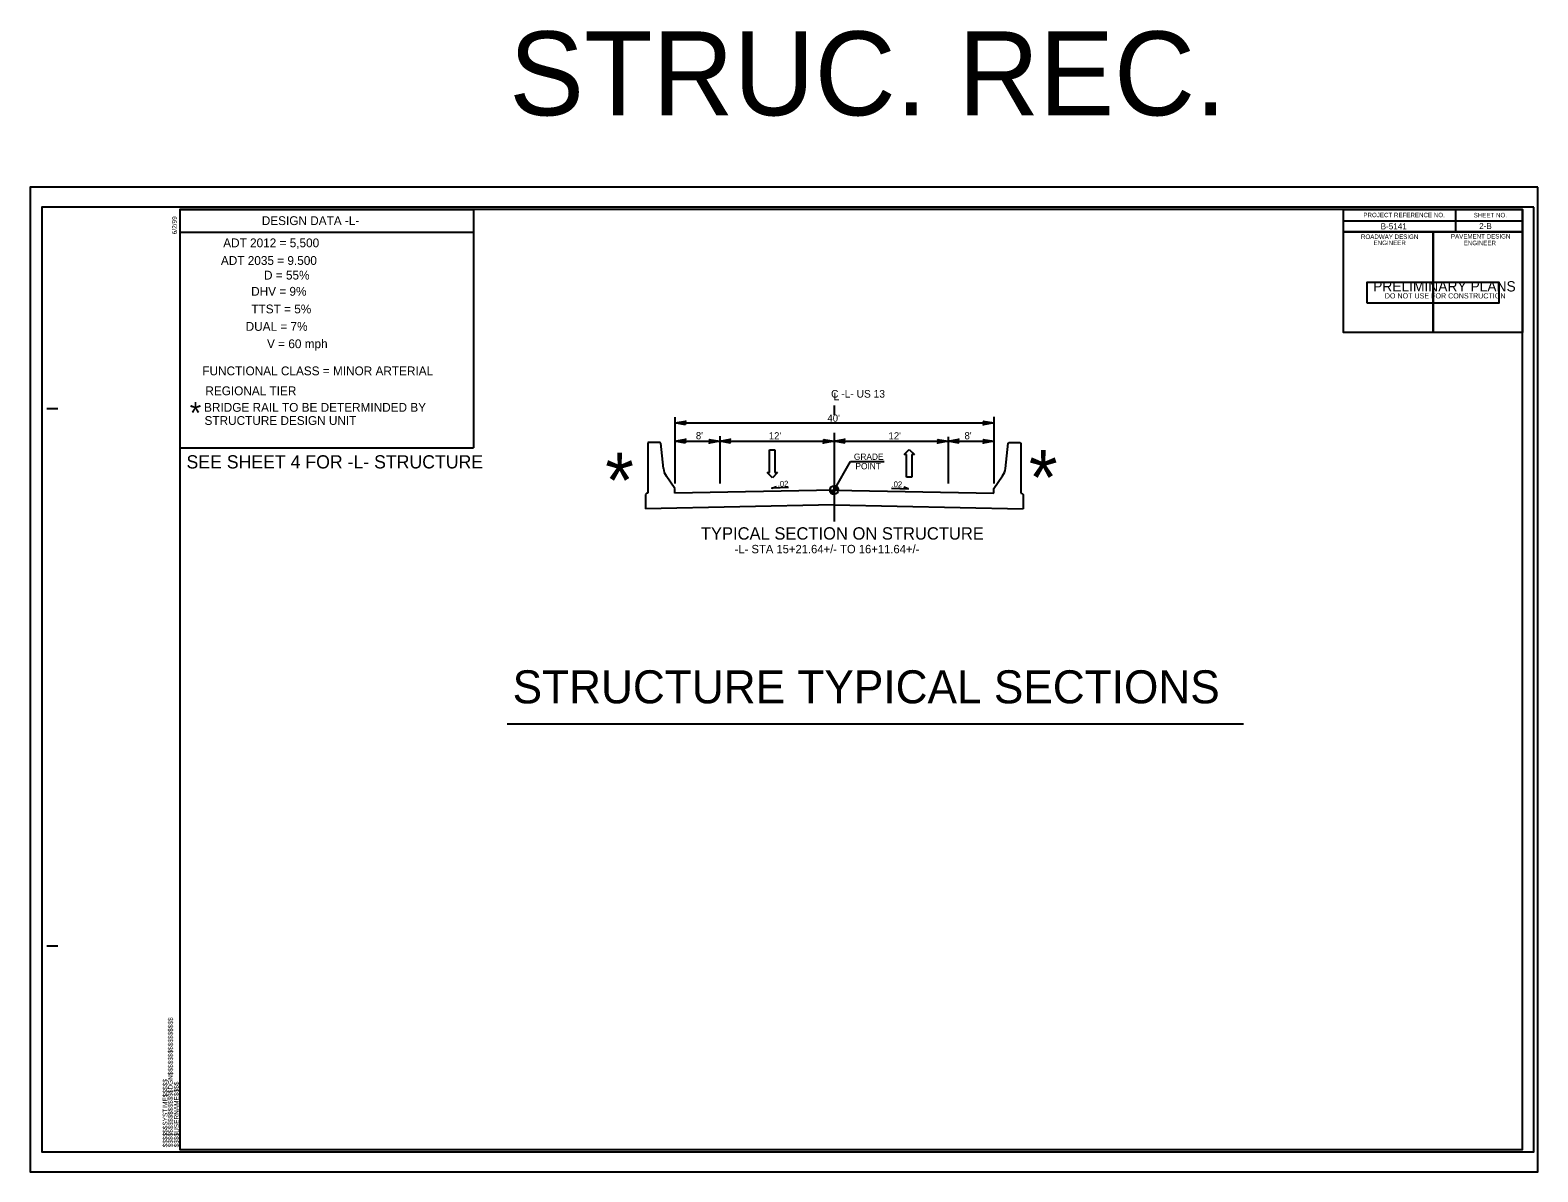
# Model space of a CAD drawing. Extents: x 9470 to 10081, y 10104 to 10463.
# Drawn here: x 9470.2 to 9739.6, y 10236.8 to 10440.9 of the extents above; entities that cross this region are included whole.
import ezdxf

# ---------------------------------------------------------------- set-up
doc = ezdxf.new("R2010")
doc.units = 0
for name, color, linetype in [('Default', 7, 'Continuous'), ('Old_Level_1', 7, 'Continuous'), ('Old_Level_11', 7, 'Continuous'), ('Old_Level_2', 7, 'Continuous'), ('Old_Level_3', 7, 'Continuous'), ('Old_Level_32', 7, 'Continuous'), ('Old_Level_33', 7, 'Continuous'), ('Prop Dimension Text', 7, 'Continuous'), ('Sheet Cutting Line CELL', 7, 'Continuous'), ('Sheet Data Field CELL', 7, 'Continuous'), ('Sheet Plot Border Inside CELL', 7, 'Continuous'), ('Sheet Plot Border Outside CELL', 7, 'Continuous'), ('Sheet Sticker Preliminary CELL', 7, 'Continuous'), ('Sheet Typical CELL', 7, 'Continuous'), ('Typical Terminator CELL', 7, 'Continuous'), ('Typical Text Grade Point CELL', 7, 'Continuous')]:
    doc.layers.add(name, color=color, linetype=linetype)

msp = doc.modelspace()

# ---------------------------------------------------------------- linework, layer by layer
at = {"layer": 'Default'}
for p, q in [((9602.36, 10361.79), (9602.36, 10365.83)), ((9602.36, 10365.83), (9603.31, 10365.83)), ((9603.31, 10365.83), (9603.31, 10361.79)), ((9626.41, 10365.01), (9627.3, 10365.92)), ((9627.3, 10365.92), (9628.23, 10365.01)), ((9626.84, 10365.01), (9626.41, 10365.01)), ((9626.84, 10360.97), (9626.84, 10365.01)), ((9628.23, 10365.01), (9627.79, 10365.01)), ((9627.79, 10365.01), (9627.79, 10360.97)), ((9602.85, 10360.88), (9601.93, 10361.79)), ((9601.93, 10361.79), (9602.36, 10361.79)), ((9603.75, 10361.79), (9602.85, 10360.88)), ((9603.31, 10361.79), (9603.75, 10361.79)), ((9627.79, 10360.97), (9626.84, 10360.97))]:
    msp.add_line(p, q, dxfattribs=at)
at = {"layer": 'Old_Level_1'}
for p, q in [((9613.87, 10373.79), (9613.87, 10372.13)), ((9585.44, 10371.69), (9585.44, 10359.83)), ((9642.42, 10371.76), (9642.42, 10359.83)), ((9585.44, 10370.66), (9642.42, 10370.66)), ((9593.47, 10368.33), (9593.47, 10359.83)), ((9613.87, 10368.88), (9613.87, 10353.08)), ((9634.27, 10370.66), (9637.67, 10370.66)), ((9634.27, 10368.17), (9634.27, 10359.83)), ((9580.72, 10367.19), (9580.61, 10367.09)), ((9580.61, 10367.09), (9580.61, 10358.11)), ((9582.78, 10367.19), (9580.72, 10367.19)), ((9582.9, 10367.07), (9582.78, 10367.19)), ((9583.38, 10362.53), (9582.9, 10367.07)), ((9585.44, 10367.4), (9593.47, 10367.4)), ((9593.47, 10367.4), (9613.87, 10367.4)), ((9613.87, 10367.4), (9634.27, 10367.4)), ((9634.27, 10367.4), (9642.42, 10367.4)), ((9644.49, 10362.53), (9644.97, 10367.07)), ((9644.97, 10367.07), (9645.09, 10367.19)), ((9645.09, 10367.19), (9647.14, 10367.19)), ((9647.14, 10367.19), (9647.25, 10367.08)), ((9647.25, 10367.08), (9647.25, 10358.11)), ((9613.87, 10358.68), (9616.8, 10363.8)), ((9585.44, 10358.97), (9583.87, 10361.2)), ((9642.42, 10358.96), (9643.99, 10361.2)), ((9580.4, 10358.11), (9580.19, 10357.9)), ((9580.19, 10357.9), (9580.19, 10356.41)), ((9580.61, 10358.11), (9580.4, 10358.11)), ((9585.44, 10358.11), (9585.44, 10358.97)), ((9613.87, 10358.68), (9585.44, 10358.11)), ((9613.1, 10358.68), (9613.87, 10358.68)), ((9613.87, 10358.68), (9613.87, 10359.45)), ((9614.63, 10358.68), (9613.87, 10358.68)), ((9613.87, 10357.92), (9613.87, 10358.68)), ((9613.87, 10358.68), (9613.87, 10357.92)), ((9613.87, 10358.68), (9642.42, 10358.11)), ((9642.42, 10358.11), (9642.42, 10358.96)), ((9647.25, 10358.11), (9647.46, 10358.11)), ((9647.46, 10358.11), (9647.67, 10357.9)), ((9647.67, 10357.9), (9647.67, 10356.41)), ((9580.19, 10356.41), (9580.19, 10355.34)), ((9613.87, 10356.01), (9580.19, 10355.34)), ((9613.87, 10356.01), (9647.67, 10355.34)), ((9647.67, 10356.41), (9647.67, 10355.34))]:
    msp.add_line(p, q, dxfattribs=at)
for points in [[(9605.76, 10359.1), (9602.78, 10359), (9603.56, 10359.29)], [(9613.11, 10358.68), (9613.11, 10358.6)], [(9613.12, 10358.68), (9613.12, 10358.51)], [(9613.14, 10358.68), (9613.14, 10358.45)], [(9613.15, 10358.68), (9613.15, 10358.41)], [(9613.17, 10358.68), (9613.17, 10358.37)], [(9613.18, 10358.68), (9613.18, 10358.34)], [(9613.2, 10358.68), (9613.2, 10358.31)], [(9613.21, 10358.68), (9613.21, 10358.28)], [(9613.23, 10358.68), (9613.23, 10358.26)], [(9613.24, 10358.68), (9613.24, 10358.24)], [(9613.26, 10358.68), (9613.26, 10358.22)], [(9613.27, 10358.68), (9613.27, 10358.2)], [(9613.29, 10358.68), (9613.29, 10358.18)], [(9613.31, 10358.68), (9613.31, 10358.16)], [(9613.32, 10358.68), (9613.32, 10358.15)], [(9613.34, 10358.68), (9613.34, 10358.13)], [(9613.35, 10358.68), (9613.35, 10358.12)], [(9613.37, 10358.68), (9613.37, 10358.1)], [(9613.38, 10358.68), (9613.38, 10358.09)], [(9613.4, 10358.68), (9613.4, 10358.08)], [(9613.41, 10358.68), (9613.41, 10358.07)], [(9613.43, 10358.68), (9613.43, 10358.06)], [(9613.44, 10358.68), (9613.44, 10358.05)], [(9613.46, 10358.68), (9613.46, 10358.04)], [(9613.47, 10358.68), (9613.47, 10358.03)], [(9613.49, 10358.68), (9613.49, 10358.02)], [(9613.5, 10358.68), (9613.5, 10358.01)], [(9613.52, 10358.68), (9613.52, 10358)], [(9613.53, 10358.68), (9613.53, 10357.99)], [(9613.55, 10358.68), (9613.55, 10357.99)], [(9613.57, 10358.68), (9613.57, 10357.98)], [(9613.58, 10358.68), (9613.58, 10357.97)], [(9613.6, 10358.68), (9613.6, 10357.97)], [(9613.61, 10358.68), (9613.61, 10357.96)], [(9613.63, 10358.68), (9613.63, 10357.96)], [(9613.64, 10358.68), (9613.64, 10357.95)], [(9613.66, 10358.68), (9613.66, 10357.95)], [(9613.67, 10358.68), (9613.67, 10357.94)], [(9613.69, 10358.68), (9613.69, 10357.94)], [(9613.7, 10358.68), (9613.7, 10357.94)], [(9613.72, 10358.68), (9613.72, 10357.93)], [(9613.73, 10358.68), (9613.73, 10357.93)], [(9613.75, 10358.68), (9613.75, 10357.93)], [(9613.76, 10358.68), (9613.76, 10357.92)], [(9613.78, 10358.68), (9613.78, 10357.92)], [(9613.8, 10358.68), (9613.8, 10357.92)], [(9613.81, 10358.68), (9613.81, 10357.92)], [(9613.83, 10358.68), (9613.83, 10357.92)], [(9613.84, 10358.68), (9613.84, 10357.92)], [(9613.86, 10358.68), (9613.86, 10357.92), (9613.86, 10357.92)], [(9613.87, 10359.45), (9613.87, 10359.45), (9613.87, 10358.68)], [(9613.89, 10359.45), (9613.89, 10358.68)], [(9613.91, 10359.45), (9613.91, 10358.68)], [(9613.92, 10359.45), (9613.92, 10358.68)], [(9613.94, 10359.44), (9613.94, 10358.68)], [(9613.95, 10359.44), (9613.95, 10358.68)], [(9613.97, 10359.44), (9613.97, 10358.68)], [(9613.98, 10359.44), (9613.98, 10358.68)], [(9614, 10359.44), (9614, 10358.68)], [(9614.01, 10359.43), (9614.01, 10358.68)], [(9614.03, 10359.43), (9614.03, 10358.68)], [(9614.04, 10359.43), (9614.04, 10358.68)], [(9614.06, 10359.42), (9614.06, 10358.68)], [(9614.07, 10359.42), (9614.07, 10358.68)], [(9614.09, 10359.42), (9614.09, 10358.68)], [(9614.1, 10359.41), (9614.1, 10358.68)], [(9614.12, 10359.4), (9614.12, 10358.68)], [(9614.14, 10359.4), (9614.14, 10358.68)], [(9614.15, 10359.39), (9614.15, 10358.68)], [(9614.17, 10359.39), (9614.17, 10358.68)], [(9614.18, 10359.38), (9614.18, 10358.68)], [(9614.2, 10359.37), (9614.2, 10358.68)], [(9614.21, 10359.37), (9614.21, 10358.68)], [(9614.23, 10359.36), (9614.23, 10358.68)], [(9614.24, 10359.35), (9614.24, 10358.68)], [(9614.26, 10359.34), (9614.26, 10358.68)], [(9614.27, 10359.33), (9614.27, 10358.68)], [(9614.29, 10359.32), (9614.29, 10358.68)], [(9614.3, 10359.31), (9614.3, 10358.68)], [(9614.32, 10359.3), (9614.32, 10358.68)], [(9614.33, 10359.29), (9614.33, 10358.68)], [(9614.35, 10359.28), (9614.35, 10358.68)], [(9614.36, 10359.26), (9614.36, 10358.68)], [(9614.38, 10359.25), (9614.38, 10358.68)], [(9614.4, 10359.24), (9614.4, 10358.68)], [(9614.41, 10359.22), (9614.41, 10358.68)], [(9614.43, 10359.21), (9614.43, 10358.68)], [(9614.44, 10359.19), (9614.44, 10358.68)], [(9614.46, 10359.17), (9614.46, 10358.68)], [(9614.47, 10359.15), (9614.47, 10358.68)], [(9614.49, 10359.13), (9614.49, 10358.68)], [(9614.5, 10359.11), (9614.5, 10358.68)], [(9614.52, 10359.09), (9614.52, 10358.68)], [(9614.53, 10359.06), (9614.53, 10358.68)], [(9614.55, 10359.03), (9614.55, 10358.68)], [(9614.56, 10359), (9614.56, 10358.68)], [(9614.58, 10358.96), (9614.58, 10358.68)], [(9614.59, 10358.92), (9614.59, 10358.68)], [(9614.61, 10358.87), (9614.61, 10358.68)], [(9614.62, 10358.79), (9614.62, 10358.68)], [(9624.12, 10358.98), (9627.09, 10358.87), (9626.32, 10359.17)]]:
    msp.add_lwpolyline(points, dxfattribs=at)
msp.add_circle((9613.87, 10358.68), 0.765, dxfattribs=at)
for centre, radius, start, end in [((9586.2, 10362.83), 2.84, 186.0111, 214.9913), ((9641.66, 10362.83), 2.84, 325.0087, 353.9889), ((9613.87, 10358.68), 0.765, 179.9905, 269.9905), ((9613.87, 10358.68), 0.765, 359.9905, 89.9905)]:
    msp.add_arc(centre, radius, start, end, dxfattribs=at)
at = {"layer": 'Old_Level_11'}
for p, q in [((9496.93, 10408.82), (9549.42, 10408.82)), ((9496.93, 10408.82), (9496.93, 10366.23)), ((9549.42, 10408.82), (9549.42, 10366.23)), ((9496.93, 10404.77), (9549.42, 10404.77)), ((9496.93, 10366.23), (9549.42, 10366.23))]:
    msp.add_line(p, q, dxfattribs=at)
at = {"layer": 'Old_Level_3'}
msp.add_line((9616.8, 10363.8), (9622.85, 10363.8), dxfattribs=at)
at = {"layer": 'Old_Level_33'}
msp.add_line((9555.48, 10316.91), (9687.07, 10316.91), dxfattribs=at)
at = {"layer": 'Sheet Cutting Line CELL'}
for p, q in [((9739.65, 10412.82), (9470.21, 10412.82)), ((9470.21, 10412.82), (9470.21, 10236.82)), ((9470.21, 10236.82), (9739.65, 10236.82))]:
    msp.add_line(p, q, dxfattribs=at)
at = {"layer": 'Sheet Plot Border Inside CELL'}
msp.add_lwpolyline([(9738.93, 10409.23), (9472.29, 10409.23), (9472.29, 10240.41), (9738.93, 10240.41)], close=True, dxfattribs=at)
at = {"layer": 'Sheet Plot Border Outside CELL'}
msp.add_lwpolyline([(9739.65, 10412.82), (9470.21, 10412.82), (9470.21, 10236.82), (9739.65, 10236.82)], close=True, dxfattribs=at)
at = {"layer": 'Sheet Sticker Preliminary CELL'}
msp.add_lwpolyline([(9709.17, 10392.05), (9709.17, 10395.81), (9732.69, 10395.81), (9732.69, 10392.05)], close=True, dxfattribs=at)
at = {"layer": 'Sheet Typical CELL'}
for p, q in [((9724.93, 10408.81), (9724.93, 10404.81)), ((9704.92, 10406.81), (9736.93, 10406.81)), ((9720.93, 10404.81), (9720.93, 10386.82)), ((9473.17, 10373.22), (9475.17, 10373.22)), ((9473.17, 10277.22), (9475.17, 10277.22)), ((9496.93, 10240.82), (9496.93, 10240.82)), ((9496.93, 10240.82), (9496.93, 10240.82)), ((9496.93, 10240.82), (9496.93, 10240.82)), ((9496.93, 10240.82), (9496.93, 10240.82)), ((9496.93, 10240.82), (9496.93, 10240.82)), ((9496.93, 10240.82), (9496.93, 10240.82))]:
    msp.add_line(p, q, dxfattribs=at)
for points in [[(9736.93, 10408.82), (9496.93, 10408.82), (9496.93, 10240.82), (9736.93, 10240.82)], [(9704.92, 10408.82), (9736.93, 10408.82), (9736.93, 10404.81), (9704.92, 10404.81)], [(9704.92, 10404.81), (9720.93, 10404.81), (9720.93, 10386.81), (9704.92, 10386.81)], [(9720.93, 10404.81), (9736.93, 10404.81), (9736.93, 10386.81), (9720.93, 10386.81)]]:
    msp.add_lwpolyline(points, close=True, dxfattribs=at)
msp.add_lwpolyline([(9502.93, 10240.82), (9502.93, 10240.82)], dxfattribs=at)
at = {"layer": 'Typical Terminator CELL'}
for points in [[(9587.35, 10370.33), (9585.44, 10370.66), (9587.36, 10371), (9587.12, 10370.66)], [(9640.51, 10370.99), (9642.42, 10370.66), (9640.5, 10370.32), (9640.75, 10370.66)], [(9587.35, 10367.07), (9585.44, 10367.4), (9587.36, 10367.74), (9587.12, 10367.4)], [(9591.56, 10367.73), (9593.47, 10367.4), (9591.55, 10367.06), (9591.79, 10367.4)], [(9595.38, 10367.07), (9593.47, 10367.4), (9595.39, 10367.74), (9595.15, 10367.4)], [(9611.96, 10367.73), (9613.87, 10367.4), (9611.95, 10367.06), (9612.19, 10367.4)], [(9615.78, 10367.07), (9613.87, 10367.4), (9615.79, 10367.74), (9615.55, 10367.4)], [(9632.36, 10367.73), (9634.27, 10367.4), (9632.35, 10367.06), (9632.59, 10367.4)], [(9636.18, 10367.07), (9634.27, 10367.4), (9636.19, 10367.74), (9635.95, 10367.4)], [(9640.51, 10367.73), (9642.42, 10367.4), (9640.5, 10367.06), (9640.75, 10367.4)]]:
    msp.add_lwpolyline(points, close=True, dxfattribs=at)

# ---------------------------------------------------------------- texts
at = {"layer": 'Old_Level_1'}
for s, height, p in [('STRUC. REC.', 15, (9555.81, 10425.64)), ('C -L- US 13', 1.3647, (9613.34, 10375.19)), ("40'", 1.275, (9612.69, 10370.89)), ("8'", 1.275, (9589.18, 10367.75)), ("12'", 1.275, (9602.21, 10367.73)), ("12'", 1.275, (9623.61, 10367.73)), ("8'", 1.275, (9637.19, 10367.75))]:
    msp.add_text(s, height=height, dxfattribs=at).set_placement(p)
msp.add_text('L', height=1.37, rotation=359.9469, dxfattribs=at).set_placement((9613.79, 10374.72))
at = {"layer": 'Old_Level_2'}
for rotation, p in [(1.144, (9603.82, 10359.27)), (358.856, (9624.14, 10359.21))]:
    msp.add_text('.02  ', height=1.02, rotation=rotation, dxfattribs=at).set_placement(p)
at = {"layer": 'Old_Level_3'}
for s, height, p in [('DESIGN DATA -L-', 1.5748, (9511.6, 10406.03)), ('FUNCTIONAL CLASS = MINOR ARTERIAL', 1.5748, (9500.98, 10379.18)), ('REGIONAL TIER', 1.5748, (9501.52, 10375.62)), ('* ', 3.937, (9498.73, 10370.5)), ('BRIDGE RAIL TO BE DETERMINDED BY', 1.5748, (9501.29, 10372.66)), ('STRUCTURE DESIGN UNIT', 1.5748, (9501.37, 10370.31)), ('* ', 9.843, (9648.69, 10356.01)), ('* ', 9.843, (9572.98, 10355.5))]:
    msp.add_text(s, height=height, rotation=360, dxfattribs=at).set_placement(p)
for s, height, p in [('ADT 2012 = 5,500', 1.5748, (9504.71, 10402.06)), ('ADT 2035 = 9.500', 1.5748, (9504.3, 10398.91)), ('D = 55%', 1.575, (9512, 10396.29)), ('DHV = 9%', 1.575, (9509.7, 10393.4)), ('TTST = 5%', 1.575, (9509.74, 10390.25)), ('DUAL = 7%', 1.575, (9508.72, 10387.13)), ('V = 60 mph', 1.575, (9512.54, 10384.03)), ('STRUCTURE TYPICAL SECTIONS', 5.9055, (9556.43, 10320.55))]:
    msp.add_text(s, height=height, dxfattribs=at).set_placement(p)
at = {"layer": 'Old_Level_32'}
for s, height, p in [('TYPICAL SECTION ON STRUCTURE', 2.21, (9590.07, 10349.81)), ('-L- STA 15+21.64+/- TO 16+11.64+/-', 1.5, (9596.11, 10347.37))]:
    msp.add_text(s, height=height, dxfattribs=at).set_placement(p)
at = {"layer": 'Prop Dimension Text'}
for s, p in [('GRADE', (9617.42, 10364.07)), ('POINT', (9617.69, 10362.38))]:
    msp.add_text(s, height=1.115, dxfattribs=at).set_placement(p)
at = {"layer": 'Sheet Data Field CELL'}
for s, p in [('B-5141   ', (9711.56, 10405.27)), ('2-B', (9729.17, 10405.32))]:
    msp.add_text(s, height=1.08, dxfattribs=at).set_placement(p)
at = {"layer": 'Sheet Sticker Preliminary CELL'}
for s, height, p in [('PRELIMINARY PLANS', 1.8432, (9710.21, 10394.16)), ('DO NOT USE FOR CONSTRUCTION', 0.9216, (9712.3, 10392.92)), ('DO NOT USE FOR CONSTRUCTION', 0.9216, (9712.3, 10392.92))]:
    msp.add_text(s, height=height, dxfattribs=at).set_placement(p)
at = {"layer": 'Sheet Typical CELL'}
for s, p in [('6/2/99', (9496.42, 10404.38)), ('$$$$$$$$$$$$$$$$DGN$$$$$$$$$$$$$$$$', (9495.7, 10241.2)), ('$$$$$$SYSTIME$$$$$', (9494.74, 10241.2)), ('$$$$USERNAME$$$$', (9496.76, 10241.2))]:
    msp.add_text(s, height=0.84, rotation=90, dxfattribs=at).set_placement(p)
for s, p in [('PROJECT REFERENCE NO.', (9708.47, 10407.43)), ('SHEET NO.', (9728.18, 10407.41)), ('ROADWAY DESIGN', (9708.04, 10403.55)), ('ENGINEER', (9710.29, 10402.45)), ('PAVEMENT DESIGN', (9724.12, 10403.62)), ('ENGINEER', (9726.39, 10402.43))]:
    msp.add_text(s, height=0.8, dxfattribs=at).set_placement(p)
at = {"layer": 'Typical Text Grade Point CELL'}
msp.add_text('SEE SHEET 4 FOR -L- STRUCTURE', height=2.3622, dxfattribs=at).set_placement((9498.15, 10362.53))

doc.saveas('drawing.dxf')
